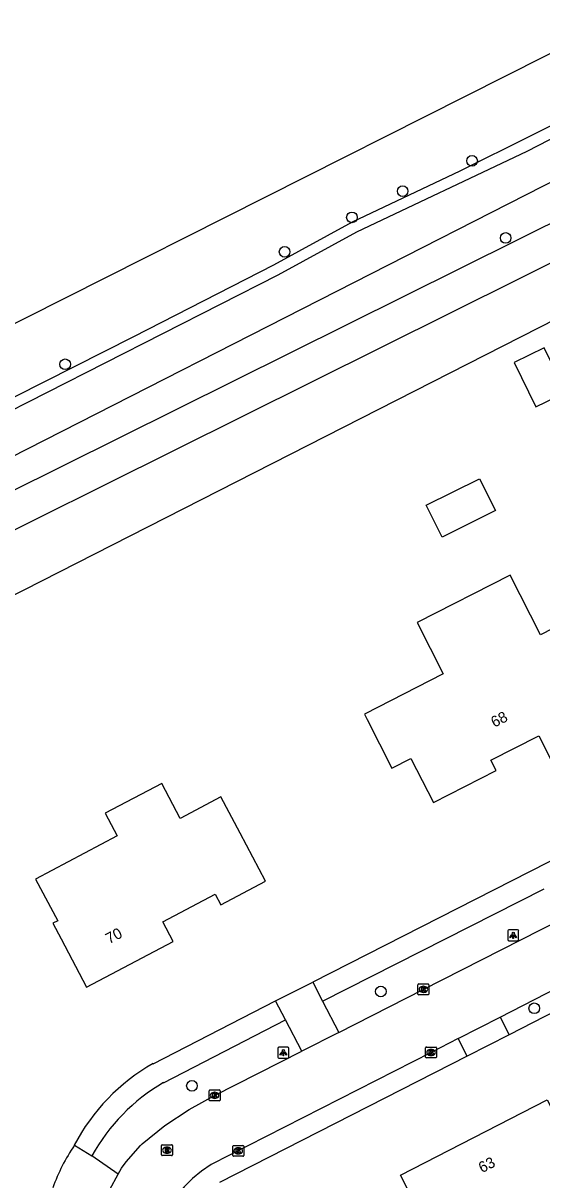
# Model space of a CAD drawing. Extents: x 162722 to 165099, y 384721 to 386283.
# Drawn here: x 163645.1 to 163692.7, y 385124 to 385230.3 of the extents above; entities that cross this region are included whole.
import ezdxf

# ---------------------------------------------------------------- set-up
doc = ezdxf.new("R2010")
doc.units = 0
for name, color, linetype in [('IMGEO_Boom', 7, 'Continuous'), ('IMGEO_Groenvoorziening', 7, 'Continuous'), ('IMGEO_Kolk', 7, 'Continuous'), ('IMGEO_Lichtpunt', 7, 'Continuous'), ('IMGEO_Loofbos', 7, 'Continuous'), ('IMGEO_Pand', 7, 'Continuous'), ('IMGEO_Pand_nummerreeks', 7, 'Continuous'), ('IMGEO_Parkeervlak_open', 7, 'Continuous'), ('IMGEO_Rijbaan_lokaal_halfverhard', 7, 'Continuous'), ('IMGEO_Rijbaan_lokaal_open', 7, 'Continuous'), ('IMGEO_Rioolput', 7, 'Continuous'), ('IMGEO_Voetpad_open', 7, 'Continuous'), ('IMGEO_Waterloop', 7, 'Continuous')]:
    doc.layers.add(name, color=color, linetype=linetype)

msp = doc.modelspace()

# ---------------------------------------------------------------- linework, layer by layer
at = {"layer": 'IMGEO_Boom'}
for centre in [(163686.33, 385217.62), (163679.95, 385214.84), (163675.29, 385212.43), (163689.42, 385210.54), (163669.1, 385209.26), (163648.93, 385198.93), (163677.95, 385141.29), (163692.05, 385139.75), (163660.58, 385132.62)]:
    msp.add_circle(centre, 0.489, dxfattribs=at)
at = {"layer": 'IMGEO_Groenvoorziening'}
msp.add_lwpolyline([(163559.75, 385137.09), (163591.68, 385153.26), (163626.17, 385170.85), (163627.13, 385169.05), (163697.36, 385204.78), (163718.26, 385215.24)], dxfattribs=at)
at = {"layer": 'IMGEO_Kolk'}
for p, q in [((163681.35, 385141.06), (163681.35, 385141.92)), ((163681.43, 385141.99), (163682.28, 385141.99)), ((163681.84, 385141.77), (163681.86, 385141.77)), ((163682.35, 385141.92), (163682.35, 385141.06)), ((163682.28, 385140.99), (163681.43, 385140.99)), ((163681.86, 385141.21), (163681.84, 385141.21)), ((163682.06, 385135.27), (163682.06, 385136.12)), ((163682.14, 385136.19), (163682.99, 385136.19)), ((163682.55, 385135.97), (163682.57, 385135.97)), ((163682.57, 385135.41), (163682.55, 385135.41)), ((163683.06, 385136.12), (163683.06, 385135.27)), ((163682.99, 385135.19), (163682.14, 385135.19)), ((163662.24, 385132.25), (163663.09, 385132.25)), ((163662.16, 385131.32), (163662.16, 385132.17)), ((163663.09, 385131.25), (163662.24, 385131.25)), ((163662.65, 385132.03), (163662.68, 385132.03)), ((163662.67, 385131.47), (163662.65, 385131.47)), ((163663.16, 385132.17), (163663.16, 385131.32)), ((163664.34, 385126.22), (163664.34, 385127.08)), ((163664.41, 385127.15), (163665.26, 385127.15)), ((163664.82, 385126.93), (163664.85, 385126.93)), ((163665.34, 385127.08), (163665.34, 385126.22)), ((163665.26, 385126.15), (163664.41, 385126.15)), ((163664.85, 385126.37), (163664.82, 385126.37))]:
    msp.add_line(p, q, dxfattribs=at)
for points in [[(163681.35, 385141.06), (163681.35, 385141.92)], [(163681.43, 385141.99), (163682.28, 385141.99)], [(163682.35, 385141.92), (163682.35, 385141.06)], [(163682.28, 385140.99), (163681.43, 385140.99)], [(163681.67, 385141.69), (163681.8, 385141.69), (163681.8, 385141.54), (163681.92, 385141.69), (163682.09, 385141.69), (163681.94, 385141.54), (163682.1, 385141.29), (163681.94, 385141.29), (163681.86, 385141.45), (163681.8, 385141.39), (163681.8, 385141.29), (163681.67, 385141.29), (163681.67, 385141.69)], [(163682.06, 385135.27), (163682.06, 385136.12)], [(163682.14, 385136.19), (163682.99, 385136.19)], [(163682.38, 385135.89), (163682.51, 385135.89), (163682.51, 385135.74), (163682.63, 385135.89), (163682.8, 385135.89), (163682.65, 385135.74), (163682.81, 385135.49), (163682.65, 385135.49), (163682.57, 385135.66), (163682.51, 385135.59), (163682.51, 385135.49), (163682.38, 385135.49), (163682.38, 385135.89)], [(163683.06, 385136.12), (163683.06, 385135.27)], [(163682.99, 385135.19), (163682.14, 385135.19)], [(163662.24, 385132.25), (163663.09, 385132.25)], [(163662.16, 385131.32), (163662.16, 385132.17)], [(163663.09, 385131.25), (163662.24, 385131.25)], [(163662.48, 385131.95), (163662.61, 385131.95), (163662.61, 385131.79), (163662.74, 385131.95), (163662.9, 385131.95), (163662.75, 385131.8), (163662.91, 385131.55), (163662.75, 385131.55), (163662.67, 385131.71), (163662.61, 385131.64), (163662.61, 385131.55), (163662.48, 385131.55), (163662.48, 385131.95)], [(163663.16, 385132.17), (163663.16, 385131.32)], [(163664.34, 385126.22), (163664.34, 385127.08)], [(163664.41, 385127.15), (163665.26, 385127.15)], [(163665.34, 385127.08), (163665.34, 385126.22)], [(163665.26, 385126.15), (163664.41, 385126.15)], [(163664.66, 385126.85), (163664.78, 385126.85), (163664.78, 385126.7), (163664.91, 385126.85), (163665.07, 385126.85), (163664.93, 385126.7), (163665.08, 385126.45), (163664.93, 385126.45), (163664.84, 385126.61), (163664.78, 385126.55), (163664.78, 385126.45), (163664.66, 385126.45), (163664.66, 385126.85)]]:
    msp.add_lwpolyline(points, dxfattribs=at)
for centre, start, end in [((163681.43, 385141.91), 91.552, 178.448), ((163681.43, 385141.91), 91.552, 178.448), ((163682.28, 385141.91), 1.552, 88.448), ((163682.28, 385141.91), 1.552, 88.448), ((163681.43, 385141.06), 181.552, 268.448), ((163681.43, 385141.06), 181.552, 268.448), ((163682.28, 385141.06), 271.552, 358.448), ((163682.28, 385141.06), 271.552, 358.448), ((163682.14, 385136.12), 91.552, 178.448), ((163682.14, 385136.12), 91.552, 178.448), ((163682.99, 385136.12), 1.552, 88.448), ((163682.99, 385136.12), 1.552, 88.448), ((163682.14, 385135.27), 181.552, 268.448), ((163682.14, 385135.27), 181.552, 268.448), ((163682.99, 385135.27), 271.552, 358.448), ((163682.99, 385135.27), 271.552, 358.448), ((163662.24, 385132.17), 91.552, 178.448), ((163662.24, 385132.17), 91.552, 178.448), ((163663.09, 385132.17), 1.552, 88.448), ((163663.09, 385132.17), 1.552, 88.448), ((163662.24, 385131.32), 181.552, 268.448), ((163662.24, 385131.32), 181.552, 268.448), ((163663.09, 385131.32), 271.552, 358.448), ((163663.09, 385131.32), 271.552, 358.448), ((163664.41, 385127.07), 91.552, 178.448), ((163664.41, 385127.07), 91.552, 178.448), ((163665.26, 385127.07), 1.552, 88.448), ((163665.26, 385127.07), 1.552, 88.448), ((163664.41, 385126.23), 181.552, 268.448), ((163664.41, 385126.23), 181.552, 268.448), ((163665.26, 385126.23), 271.552, 358.448), ((163665.26, 385126.23), 271.552, 358.448)]:
    msp.add_arc(centre, 0.0765, start, end, dxfattribs=at)
for centre, major_axis, ratio, start_param, end_param in [((163681.84, 385141.49), (-0.387, 0.002), 0.722429, 4.712389, 7.853982), ((163681.86, 385141.49), (-0.39, 0.002), 0.717154, 1.570796, 4.712389), ((163682.55, 385135.69), (-0.387, 0.002), 0.722429, 4.712389, 7.853982), ((163682.57, 385135.69), (-0.39, 0.002), 0.717154, 1.570796, 4.712389), ((163662.65, 385131.75), (-0.387, 0.002), 0.722429, 4.712389, 7.853982), ((163662.67, 385131.75), (-0.39, 0.002), 0.717154, 1.570796, 4.712389), ((163664.82, 385126.65), (-0.387, 0.002), 0.722429, 4.712389, 7.853982), ((163664.85, 385126.65), (-0.39, 0.002), 0.717154, 1.570796, 4.712389)]:
    msp.add_ellipse(centre, major_axis=major_axis, ratio=ratio, start_param=start_param, end_param=end_param, dxfattribs=at)
at = {"layer": 'IMGEO_Lichtpunt'}
for p, q in [((163689.62, 385146.86), (163689.62, 385146.06)), ((163689.62, 385146.86), (163689.62, 385146.06)), ((163690.52, 385146.96), (163689.71, 385146.96)), ((163690.52, 385146.96), (163689.71, 385146.96)), ((163690.61, 385146.06), (163690.61, 385146.86)), ((163690.61, 385146.06), (163690.61, 385146.86)), ((163689.71, 385145.96), (163690.52, 385145.96)), ((163689.71, 385145.96), (163690.52, 385145.96)), ((163668.49, 385136.07), (163668.49, 385135.27)), ((163668.49, 385136.07), (163668.49, 385135.27)), ((163669.39, 385136.17), (163668.58, 385136.17)), ((163669.39, 385136.17), (163668.58, 385136.17)), ((163669.48, 385135.27), (163669.48, 385136.07)), ((163669.48, 385135.27), (163669.48, 385136.07)), ((163668.58, 385135.17), (163669.39, 385135.17)), ((163668.58, 385135.17), (163669.39, 385135.17))]:
    msp.add_line(p, q, dxfattribs=at)
for points in [[(163689.99, 385146.53), (163690.03, 385146.5), (163689.84, 385146.24), (163689.8, 385146.26), (163689.99, 385146.53)], [(163690.09, 385146.48), (163690.14, 385146.48), (163690.14, 385146.16), (163690.09, 385146.16), (163690.09, 385146.48)], [(163690.2, 385146.5), (163690.24, 385146.53), (163690.43, 385146.26), (163690.39, 385146.24), (163690.2, 385146.5)], [(163668.86, 385135.74), (163668.9, 385135.71), (163668.71, 385135.45), (163668.67, 385135.47), (163668.86, 385135.74)], [(163668.96, 385135.69), (163669.01, 385135.69), (163669.01, 385135.37), (163668.96, 385135.37), (163668.96, 385135.69)], [(163669.07, 385135.71), (163669.11, 385135.74), (163669.3, 385135.47), (163669.26, 385135.45), (163669.07, 385135.71)]]:
    msp.add_lwpolyline(points, dxfattribs=at)
for centre in [(163690.12, 385146.66), (163668.99, 385135.87)]:
    msp.add_circle(centre, 0.0994, dxfattribs=at)
for centre, start, end in [((163689.71, 385146.86), 90, 180), ((163689.71, 385146.86), 90, 180), ((163689.71, 385146.06), 180, 270), ((163689.71, 385146.06), 180, 270), ((163690.52, 385146.86), 0, 90), ((163690.52, 385146.86), 0, 90), ((163690.52, 385146.06), 270, 0), ((163690.52, 385146.06), 270, 360), ((163668.58, 385136.07), 90, 180), ((163668.58, 385136.07), 90, 180), ((163669.39, 385136.07), 0, 90), ((163669.39, 385136.07), 0, 90), ((163668.58, 385135.27), 180, 270), ((163668.58, 385135.27), 180, 270), ((163669.39, 385135.27), 270, 0), ((163669.39, 385135.27), 270, 360)]:
    msp.add_arc(centre, 0.0946, start, end, dxfattribs=at)
at = {"layer": 'IMGEO_Loofbos'}
for points in [[(163582.09, 385306.8), (163581.43, 385306.48), (163540.18, 385285.87), (163543.92, 385277.3), (163557.51, 385250), (163593.93, 385177.31), (163740.78, 385251.34), (163752.79, 385257.17), (163698.9, 385364.12), (163630.39, 385330.12), (163622.47, 385326.2)], [(163757.39, 385253.34), (163752.2, 385250.91), (163745.06, 385247.55), (163737.48, 385243.67), (163734.23, 385241.98), (163722.21, 385235.5), (163717.57, 385233.01), (163716.25, 385232.35), (163712.96, 385230.75), (163710.13, 385229.29), (163698.25, 385223.18), (163685.2, 385216.69), (163675.32, 385212), (163668.07, 385208.03), (163655.21, 385201.44), (163641.53, 385194.55), (163632.4, 385189.72), (163621.09, 385184.05), (163617.29, 385182.39), (163610.79, 385178.78), (163603.26, 385174.96), (163593.86, 385170.65)]]:
    msp.add_lwpolyline(points, dxfattribs=at)
at = {"layer": 'IMGEO_Pand'}
for points in [[(163690.2, 385199.09), (163692.2, 385195.02), (163694.97, 385196.38), (163692.97, 385200.45), (163690.2, 385199.09)], [(163687.01, 385188.41), (163688.47, 385185.48), (163683.57, 385183.04), (163682.11, 385185.97), (163687.01, 385188.41)], [(163678.96, 385161.83), (163680.7, 385162.71), (163682.77, 385158.65), (163688.55, 385161.59), (163688.06, 385162.54), (163692.46, 385164.78), (163693.63, 385162.49), (163698.65, 385165.05), (163696.37, 385169.5), (163693.75, 385174.64), (163692.62, 385174.07), (163689.82, 385179.55), (163681.28, 385175.19), (163683.68, 385170.48), (163676.43, 385166.78), (163676.68, 385166.28), (163678.96, 385161.83)], [(163667.35, 385151.42), (163665.01, 385155.84), (163663.25, 385159.18), (163659.5, 385157.2), (163657.8, 385160.42), (163652.61, 385157.68), (163653.71, 385155.59), (163646.21, 385151.63), (163648.24, 385147.79), (163647.8, 385147.56), (163648.57, 385146.12), (163650.9, 385141.69), (163658.84, 385145.89), (163657.89, 385147.7), (163662.72, 385150.25), (163663.25, 385149.25), (163667.35, 385151.42)], [(163683.73, 385116.63), (163682.02, 385119.98), (163679.74, 385124.43), (163693.23, 385131.33), (163695.51, 385126.88), (163696.64, 385124.66), (163698.68, 385120.67), (163694.66, 385118.61), (163694.12, 385119.67), (163690.33, 385117.73), (163689.4, 385119.53), (163683.73, 385116.63)]]:
    msp.add_lwpolyline(points, dxfattribs=at)
at = {"layer": 'IMGEO_Parkeervlak_open'}
for points in [[(163704.94, 385145.12), (163689.74, 385137.3)], [(163685.87, 385135.34), (163663.11, 385123.73)]]:
    msp.add_lwpolyline(points, dxfattribs=at)
at = {"layer": 'IMGEO_Rijbaan_lokaal_halfverhard'}
for points in [[(163594.3, 385169.76), (163603.67, 385174.05), (163611.28, 385177.9), (163617.77, 385181.51), (163621.54, 385183.16), (163632.85, 385188.83), (163641.98, 385193.66), (163668.52, 385207.14), (163675.75, 385211.1), (163691.38, 385218.52), (163713.39, 385229.85)], [(163714.91, 385226.25), (163709.03, 385223.29), (163695.98, 385216.89), (163624.9, 385180.68), (163618.66, 385177.79), (163605.53, 385170.96), (163600.48, 385168.62), (163586.16, 385161.55), (163584.25, 385160.55)]]:
    msp.add_lwpolyline(points, dxfattribs=at)
at = {"layer": 'IMGEO_Rijbaan_lokaal_open'}
for points in [[(163674.08, 385137.54), (163681.85, 385141.49), (163694.43, 385147.88)], [(163688.91, 385138.95), (163702.67, 385146.02), (163704.11, 385146.77)], [(163685.04, 385136.96), (163688.91, 385138.95)], [(163674.08, 385137.54), (163670.69, 385135.82)], [(163685.04, 385136.96), (163682.56, 385135.69), (163662.36, 385125.4), (163661.46, 385124.79), (163660.63, 385124.11), (163659.87, 385123.35), (163659.17, 385122.53), (163658.55, 385121.65), (163658.01, 385120.71), (163657.55, 385119.73), (163657.19, 385118.72), (163656.92, 385117.68), (163656.74, 385116.61), (163656.66, 385115.6), (163656.64, 385111.26), (163656.58, 385098.28), (163656.58, 385096.67)], [(163653.79, 385124.5), (163654.11, 385125.06), (163654.53, 385125.63), (163655.84, 385127.15), (163656.01, 385127.3), (163658.09, 385128.98), (163660.31, 385130.46), (163662.66, 385131.75), (163670.69, 385135.82)], [(163651.23, 385116), (163651.3, 385117.06), (163651.53, 385118.63), (163651.89, 385120.17), (163652.4, 385121.67), (163653.03, 385123.11), (163653.79, 385124.5)]]:
    msp.add_lwpolyline(points, dxfattribs=at)
at = {"layer": 'IMGEO_Rioolput'}
for p, q in [((163657.79, 385126.29), (163657.79, 385127.14)), ((163657.86, 385127.21), (163658.71, 385127.21)), ((163658.27, 385126.99), (163658.3, 385126.99)), ((163658.79, 385127.14), (163658.79, 385126.29)), ((163658.71, 385126.21), (163657.86, 385126.21)), ((163658.3, 385126.43), (163658.27, 385126.43))]:
    msp.add_line(p, q, dxfattribs=at)
for points in [[(163657.79, 385126.29), (163657.79, 385127.14)], [(163657.86, 385127.21), (163658.71, 385127.21)], [(163658.37, 385126.91), (163658.12, 385126.91), (163658.12, 385126.51)], [(163658.79, 385127.14), (163658.79, 385126.29)], [(163658.71, 385126.21), (163657.86, 385126.21)], [(163658.12, 385126.51), (163658.25, 385126.51), (163658.25, 385126.67), (163658.26, 385126.67)], [(163658.3, 385126.83), (163658.25, 385126.83), (163658.25, 385126.75)], [(163658.25, 385126.75), (163658.3, 385126.75)], [(163658.3, 385126.64), (163658.38, 385126.51), (163658.51, 385126.51), (163658.45, 385126.64)]]:
    msp.add_lwpolyline(points, dxfattribs=at)
for centre, radius, start, end in [((163657.86, 385127.14), 0.0765, 91.552, 178.448), ((163657.86, 385127.14), 0.0765, 91.552, 178.448), ((163658.37, 385126.8), 0.109, 350.3612, 89.416), ((163658.71, 385127.14), 0.0765, 1.552, 88.448), ((163658.71, 385127.14), 0.0765, 1.552, 88.448), ((163657.86, 385126.29), 0.0765, 181.552, 268.448), ((163657.86, 385126.29), 0.0765, 181.552, 268.448), ((163658.26, 385126.62), 0.0533, 26.0293, 88.6989), ((163658.31, 385126.73), 0.0964, 77.0061, 93.1865), ((163658.28, 385126.94), 0.19, 274.7715, 282.9687), ((163658.32, 385126.79), 0.0378, 276.6634, 79.6772), ((163658.37, 385126.8), 0.112, 277.5842, 350.9817), ((163658.36, 385126.58), 0.108, 29.5134, 73.7905), ((163658.71, 385126.29), 0.0765, 271.552, 358.448), ((163658.71, 385126.29), 0.0765, 271.552, 358.448)]:
    msp.add_arc(centre, radius, start, end, dxfattribs=at)
for centre, major_axis, ratio, start_param, end_param in [((163658.27, 385126.71), (-0.387, 0.002), 0.722429, 4.712389, 7.853982), ((163658.3, 385126.71), (-0.39, 0.002), 0.717154, 1.570796, 4.712389)]:
    msp.add_ellipse(centre, major_axis=major_axis, ratio=ratio, start_param=start_param, end_param=end_param, dxfattribs=at)
at = {"layer": 'IMGEO_Voetpad_open'}
for points in [[(163698.29, 385155.7), (163671.69, 385142.14)], [(163672.59, 385140.41), (163692.96, 385150.74)], [(163668.26, 385140.43), (163671.69, 385142.14)], [(163671.69, 385142.14), (163672.59, 385140.41)], [(163657.01, 385134.66), (163668.26, 385140.43)], [(163669.18, 385138.69), (163668.26, 385140.43)], [(163672.59, 385140.41), (163674.08, 385137.54)], [(163657.96, 385132.91), (163669.18, 385138.69)], [(163670.69, 385135.82), (163669.18, 385138.69)], [(163688.91, 385138.95), (163689.74, 385137.3)], [(163685.87, 385135.34), (163685.04, 385136.96)], [(163689.74, 385137.3), (163685.87, 385135.34)], [(163649.77, 385127.17), (163651.38, 385126.18)], [(163653.79, 385124.5), (163651.38, 385126.18)]]:
    msp.add_lwpolyline(points, dxfattribs=at)
for centre, radius, start, end in [((163666.11, 385118.62), 18.45, 119.5653, 152.3863), ((163666.89, 385117.61), 17.72, 120.253, 151.0554), ((163664.37, 385117.29), 17.62, 145.9272, 160.1933)]:
    msp.add_arc(centre, radius, start, end, dxfattribs=at)
at = {"layer": 'IMGEO_Waterloop'}
for points in [[(163716.62, 385223.33), (163580.89, 385155.91)], [(163716.14, 385219.46), (163582.61, 385153.07), (163572.28, 385147.71), (163567.28, 385144.31), (163558.1, 385140.33)]]:
    msp.add_lwpolyline(points, dxfattribs=at)

# ---------------------------------------------------------------- texts
at = {"layer": 'IMGEO_Pand_nummerreeks'}
for s, rotation, p in [('68', 27.0427, (163688.38, 385165.53)), ('70', 27.84, (163652.97, 385145.63)), ('63', 27.0909, (163687.24, 385124.59))]:
    msp.add_text(s, height=1, rotation=rotation, dxfattribs=at).set_placement(p)

doc.saveas('drawing.dxf')
